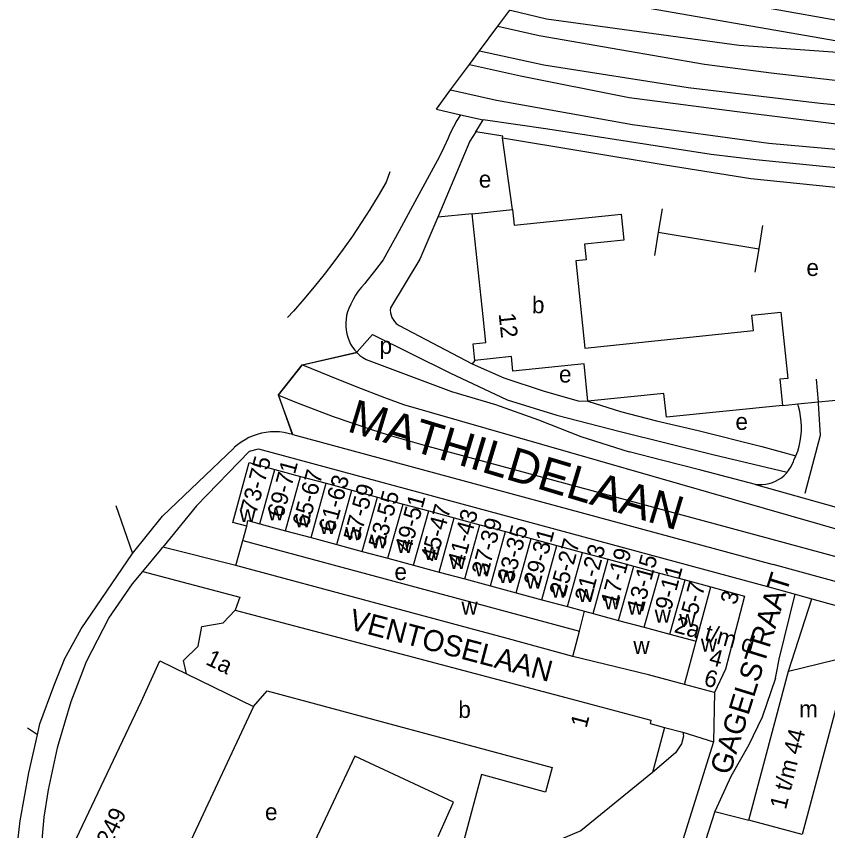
# Model space of a CAD drawing. Extents: x 160673 to 161924, y 382258 to 384145.
# Drawn here: x 160684.6 to 160877.2, y 383510.1 to 383703.4 of the extents above; entities that cross this region are included whole.
import ezdxf

# ---------------------------------------------------------------- set-up
doc = ezdxf.new("R2010")
doc.units = 0
for name, color, linetype in [('BLT_Basislijn', 7, 'Continuous'), ('BLT_Bebouwing', 7, 'Continuous'), ('BLT_Centroide', 7, 'Continuous'), ('BLT_Huisnummer', 7, 'Continuous'), ('BLT_Huisnummer_reeks', 7, 'Continuous'), ('BLT_Huisnummer_zonder_bebouwing', 7, 'Continuous'), ('BLT_Onderverdeling_panden', 7, 'Continuous'), ('BLT_Plantopo', 7, 'Continuous'), ('BLT_Spoorlijn', 7, 'Continuous'), ('BLT_Straatnaam', 7, 'Continuous'), ('BLT_Straatnaam_hoofdweg', 7, 'Continuous'), ('BLT_Vlakafsluiter', 7, 'Continuous')]:
    doc.layers.add(name, color=color, linetype=linetype)

msp = doc.modelspace()

# ---------------------------------------------------------------- linework, layer by layer
at = {"layer": 'BLT_Basislijn'}
for p, q in [((160784.31, 383681.42), (160790.04, 383680.08)), ((160790.04, 383680.08), (160795.38, 383678.83)), ((160793.67, 383676.01), (160795.38, 383678.83)), ((160802.36, 383657.57), (160800.02, 383674.62)), ((160784.45, 383669.14), (160779.18, 383659.38)), ((160773.28, 383666.54), (160772.4, 383664.07)), ((160792.82, 383656.58), (160784.62, 383655.77)), ((160837.89, 383657.72), (160836.97, 383652.2)), ((160861.71, 383653.74), (160860.79, 383648.23)), ((160836.97, 383652.2), (160836.05, 383646.69)), ((160836.97, 383652.2), (160860.79, 383648.23)), ((160860.79, 383648.23), (160859.87, 383642.72)), ((160767.63, 383621.93), (160787.93, 383614.4)), ((160793.39, 383621.74), (160792.83, 383620.95)), ((160874.45, 383617.29), (160874.92, 383611.89)), ((160820.27, 383612.09), (160828.01, 383609.62)), ((160874.92, 383611.89), (160881.75, 383612.54)), ((160866.47, 383611.08), (160869.42, 383611.36)), ((160869.42, 383611.36), (160870.04, 383611.42)), ((160870.04, 383611.42), (160874.92, 383611.89)), ((160750.17, 383604.14), (160750.23, 383604.13)), ((160750.23, 383604.13), (160864.24, 383573.3)), ((160736.23, 383600.95), (160719.33, 383584.74)), ((160739.98, 383600.19), (160742.09, 383600.77)), ((160742.09, 383600.77), (160863.78, 383567.86)), ((160781.39, 383601.65), (160863.02, 383579.54)), ((160727.38, 383587.23), (160739.98, 383600.19)), ((160869.14, 383598.04), (160869.6, 383599.06)), ((160727.38, 383587.23), (160719.36, 383577.38)), ((160738.36, 383578.98), (160739.29, 383582.38)), ((160863.02, 383579.54), (160901.21, 383569.2)), ((160736.74, 383573.06), (160719.36, 383577.38)), ((160863.78, 383567.86), (160869.47, 383566.26)), ((160867.86, 383547.96), (160873.42, 383565.14)), ((160873.42, 383565.14), (160885.87, 383561.63)), ((160864.76, 383546.29), (160865.16, 383548.28)), ((160850.32, 383542.91), (160850.1, 383531.24)), ((160838.45, 383534.64), (160842.81, 383533.52)), ((160842.81, 383533.52), (160850.1, 383531.24)), ((160841.03, 383528.62), (160835.61, 383523.91)), ((160850.39, 383514.63), (160842.89, 383491.44)), ((160850.39, 383514.63), (160858.45, 383512.62))]:
    msp.add_line(p, q, dxfattribs=at)
for points in [[(160827.47, 383712.33), (160848.19, 383708.12), (160880.3, 383702.37), (160918.98, 383698.8)], [(160790.04, 383680.08), (160789.16, 383678.66), (160788.35, 383677.2), (160787.61, 383675.7), (160787.09, 383674.5)], [(160940.73, 383664.63), (160927.19, 383664.82), (160902.61, 383665.8), (160883.17, 383667.06), (160860.14, 383669.36), (160849.53, 383670.59), (160810.77, 383676.62), (160795.38, 383678.83)], [(160793.67, 383676.01), (160792.25, 383673.76), (160784.62, 383655.77)], [(160800.02, 383674.62), (160800.07, 383674.95), (160793.67, 383676.01)], [(160787.09, 383674.5), (160786.08, 383672.32), (160785.01, 383670.19), (160784.45, 383669.14)], [(160800.02, 383674.62), (160838.61, 383668.19)], [(160838.61, 383668.19), (160858.92, 383664.92), (160882.17, 383662.58), (160903.94, 383660.75), (160931.32, 383660.4)], [(160772.4, 383664.07), (160770.49, 383660.81), (160768.52, 383657.59), (160766.48, 383654.41), (160764.37, 383651.27), (160762.2, 383648.19), (160759.96, 383645.14), (160757.65, 383642.15), (160755.29, 383639.21), (160752.86, 383636.31), (160750.37, 383633.47), (160748.96, 383631.92)], [(160779.18, 383659.38), (160775.48, 383652.5), (160771.68, 383645.62)], [(160784.62, 383655.77), (160780.38, 383645.78), (160773.39, 383634.23)], [(160771.68, 383645.62), (160769.62, 383642.9), (160767.48, 383640.23), (160767.29, 383640.01)], [(160767.29, 383640.01), (160766.5, 383639.12), (160765.78, 383638.18), (160765.11, 383637.2), (160764.52, 383636.18), (160763.99, 383635.11), (160763.56, 383634.07)], [(160763.56, 383634.07), (160763.25, 383633.25), (160763.01, 383632.41), (160762.86, 383631.55), (160762.78, 383630.68), (160762.78, 383629.8), (160762.86, 383628.93), (160763.02, 383628.07), (160763.26, 383627.23), (160763.58, 383626.42), (160763.96, 383625.63), (160764.42, 383624.89), (160764.95, 383624.19), (160765.41, 383623.67)], [(160773.39, 383634.23), (160773.36, 383633.65), (160773.41, 383633.06), (160773.54, 383632.49), (160773.74, 383631.94), (160774.02, 383631.43), (160774.37, 383630.96), (160774.77, 383630.53), (160775.23, 383630.17), (160775.5, 383630)], [(160775.5, 383630), (160792.83, 383620.95)], [(160765.41, 383623.67), (160769.15, 383627.91), (160787.52, 383618.8), (160801.09, 383612.41), (160812.86, 383608.77), (160827.89, 383604.88), (160849.92, 383599.42), (160867.55, 383595.19)], [(160765.41, 383623.67), (160765.45, 383623.63)], [(160765.45, 383623.63), (160765.53, 383623.54), (160766.17, 383622.95), (160766.87, 383622.41), (160767.63, 383621.93)], [(160752.48, 383620.73), (160752.56, 383620.7)], [(160752.56, 383620.7), (160758.95, 383618.07), (160765.44, 383615.49), (160771.96, 383612.98), (160776.48, 383611.29), (160881.61, 383581.05)], [(160792.83, 383620.95), (160800.34, 383617.62), (160809.91, 383614.41), (160817.98, 383612.16), (160820.27, 383612.09)], [(160787.93, 383614.4), (160798.31, 383611.31), (160808.55, 383607.68), (160818.61, 383603.65), (160830.07, 383600.03)], [(160746.81, 383613.55), (160746.87, 383613.53)], [(160746.87, 383613.53), (160751.12, 383611.78), (160755.46, 383610.08), (160759.83, 383608.46), (160764.22, 383606.91), (160768.64, 383605.43), (160773.09, 383604.04), (160777.56, 383602.72), (160781.39, 383601.65)], [(160869.6, 383599.06), (160870.04, 383600.24), (160870.38, 383601.38), (160870.64, 383602.54), (160870.82, 383603.71), (160870.92, 383604.9), (160870.94, 383606.09), (160870.89, 383607.27), (160870.75, 383608.45), (160870.53, 383609.62), (160870.24, 383610.78), (160870.04, 383611.42)], [(160871.83, 383590.25), (160875.44, 383604), (160874.95, 383611.54), (160874.92, 383611.89)], [(160828.01, 383609.62), (160836.5, 383607.43), (160846.44, 383605.13), (160861.5, 383601.31)], [(160750.17, 383604.14), (160749.15, 383604.43), (160748.11, 383604.63), (160747.05, 383604.76), (160745.99, 383604.8), (160744.93, 383604.77), (160743.87, 383604.65), (160742.83, 383604.46), (160741.8, 383604.19), (160740.8, 383603.84), (160739.83, 383603.42), (160738.89, 383602.93), (160737.99, 383602.36), (160737.13, 383601.73), (160736.32, 383601.04), (160736.23, 383600.95)], [(160861.5, 383601.31), (160869.6, 383599.06)], [(160860.01, 383592.29), (160847.03, 383595.72), (160838.07, 383597.97), (160830.07, 383600.03)], [(160867.55, 383595.19), (160867.9, 383595.62), (160868.36, 383596.3), (160868.74, 383597.02), (160869.05, 383597.77), (160869.14, 383598.04)], [(160860.01, 383592.29), (160860.83, 383592.27), (160861.65, 383592.27), (160862.46, 383592.35), (160863.26, 383592.51), (160864.04, 383592.75), (160864.79, 383593.06), (160865.51, 383593.45), (160866.18, 383593.9), (160866.81, 383594.42), (160867.39, 383594.99), (160867.55, 383595.19)], [(160712.16, 383575.89), (160719.33, 383584.74)], [(160714.64, 383571.67), (160718.83, 383576.72), (160719.36, 383577.38)], [(160700, 383558.06), (160712.16, 383575.89)], [(160941.01, 383549.42), (160929.52, 383553.39), (160912.82, 383559.96), (160900.62, 383563.32), (160864.24, 383573.3)], [(160700, 383546.98), (160701.27, 383550.27), (160706.59, 383560.53), (160712.17, 383568.68), (160714.64, 383571.67)], [(160714.64, 383571.67), (160737.69, 383565.52), (160736.59, 383562.49)], [(160865.16, 383548.28), (160865.66, 383550.82), (160869.47, 383566.26)], [(160869.47, 383566.26), (160873.42, 383565.14)], [(160689.63, 383532.89), (160690.21, 383535.51), (160693.58, 383544.64), (160696.17, 383550.97), (160700, 383558.06)], [(160694.43, 383529.74), (160694.61, 383530.61), (160697.62, 383540.81), (160700, 383546.98)], [(160864.76, 383546.29), (160861.64, 383537.08), (160858.47, 383530.46), (160854.16, 383522.99), (160850.39, 383514.63)], [(160684.61, 383490.86), (160684.61, 383499.58), (160685.09, 383508.32), (160685.57, 383512.46), (160687.62, 383523.88), (160689.63, 383532.89)], [(160842.81, 383533.52), (160842.93, 383532.55), (160842.45, 383530.73), (160841.03, 383528.62)], [(160850.1, 383531.24), (160828.79, 383463.13), (160828.19, 383459.76), (160828.59, 383456.34), (160829.47, 383453.28), (160831.32, 383450.35), (160833.59, 383447.68), (160835.3, 383445.08), (160835.79, 383442.16)], [(160697.47, 383475.43), (160692.31, 383484.12), (160690.54, 383491.16), (160690.31, 383502.5), (160691.21, 383513.34), (160692.23, 383519.82), (160694.43, 383529.74)]]:
    msp.add_lwpolyline(points, dxfattribs=at)
at = {"layer": 'BLT_Bebouwing'}
for p, q in [((160802.45, 383619.2), (160802.1, 383622.64)), ((160745.98, 383595.84), (160752.06, 383594.21)), ((160752.06, 383594.21), (160758.15, 383592.57)), ((160758.15, 383592.57), (160764.23, 383590.93)), ((160764.23, 383590.93), (160770.31, 383589.29)), ((160770.31, 383589.29), (160776.4, 383587.65)), ((160776.4, 383587.65), (160782.48, 383586.01)), ((160782.48, 383586.01), (160788.56, 383584.37)), ((160742.38, 383582.97), (160748.47, 383581.33)), ((160788.56, 383584.37), (160794.65, 383582.74)), ((160748.47, 383581.33), (160754.55, 383579.69)), ((160794.65, 383582.74), (160800.73, 383581.1)), ((160800.73, 383581.1), (160806.81, 383579.46)), ((160754.55, 383579.69), (160760.64, 383578.06)), ((160806.81, 383579.46), (160812.9, 383577.82)), ((160736.74, 383573.06), (160738.36, 383578.98)), ((160738.36, 383578.98), (160818.25, 383557.46)), ((160760.64, 383578.06), (160766.72, 383576.42)), ((160812.9, 383577.82), (160818.98, 383576.18)), ((160766.72, 383576.42), (160772.8, 383574.78)), ((160818.98, 383576.18), (160825.07, 383574.54)), ((160772.8, 383574.78), (160778.89, 383573.14)), ((160825.07, 383574.54), (160831.15, 383572.9)), ((160778.89, 383573.14), (160784.97, 383571.5)), ((160784.97, 383571.5), (160791.05, 383569.86)), ((160831.15, 383572.9), (160837.23, 383571.26)), ((160791.05, 383569.86), (160797.14, 383568.22)), ((160837.23, 383571.26), (160843.32, 383569.63)), ((160843.32, 383569.63), (160849.4, 383567.99)), ((160797.14, 383568.22), (160803.22, 383566.59)), ((160803.22, 383566.59), (160809.3, 383564.95)), ((160857.46, 383565.82), (160853.81, 383551.75)), ((160809.3, 383564.95), (160815.39, 383563.31)), ((160736.59, 383562.49), (160749.16, 383559.16)), ((160815.39, 383563.31), (160819.48, 383562.21)), ((160818.25, 383557.46), (160819.48, 383562.21)), ((160749.16, 383559.16), (160777.39, 383551.68)), ((160724.99, 383547.34), (160724.26, 383550.5)), ((160777.39, 383551.68), (160815.05, 383541.71)), ((160858.45, 383512.62), (160867.86, 383547.96)), ((160838.45, 383534.64), (160835.61, 383523.91))]:
    msp.add_line(p, q, dxfattribs=at)
for points in [[(160792.82, 383656.58), (160802.36, 383657.57)], [(160795.42, 383632.17), (160792.82, 383656.58)], [(160802.36, 383657.57), (160802.75, 383653.82), (160826.68, 383656.32)], [(160826.68, 383656.32), (160828.16, 383656.48), (160828.8, 383650.32), (160819.42, 383649.34), (160819.81, 383645.63), (160817.36, 383645.37), (160819.52, 383624.68), (160859.52, 383628.86), (160859.14, 383632.45), (160866.05, 383633.17), (160867.7, 383617.45), (160865.83, 383617.26), (160866.47, 383611.08)], [(160793.39, 383621.74), (160793.04, 383625.72), (160796.06, 383626.03), (160795.42, 383632.17)], [(160802.1, 383622.64), (160793.39, 383621.74)], [(160820.27, 383612.09), (160819.37, 383620.92), (160802.45, 383619.2)], [(160838.3, 383613.93), (160820.27, 383612.09)], [(160866.47, 383611.08), (160838.88, 383608.3), (160838.3, 383613.93)], [(160739.29, 383582.38), (160735.99, 383583.28), (160739.89, 383597.5), (160745.98, 383595.84)], [(160739.29, 383582.38), (160739.57, 383583.73), (160742.38, 383582.97)], [(160816.68, 383551.44), (160801.43, 383555.62), (160736.74, 383573.06)], [(160849.4, 383567.99), (160857.46, 383565.82)], [(160728.61, 383558.56), (160733.67, 383559.48), (160736.59, 383562.49)], [(160724.26, 383550.5), (160727.77, 383553.89), (160728.61, 383558.56)], [(160843.17, 383544.85), (160834.65, 383547.07), (160816.68, 383551.44)], [(160853.81, 383551.75), (160852.92, 383548.47), (160850.32, 383542.91), (160843.17, 383544.85)], [(160867.86, 383547.96), (160882.4, 383551.52), (160871.13, 383509.23), (160858.45, 383512.62)], [(160724.99, 383547.34), (160740.93, 383539.56), (160744.15, 383543.28), (160811.79, 383525.14), (160810.21, 383519.26), (160794.99, 383523.45), (160790.82, 383507.82)], [(160815.05, 383541.71), (160835.22, 383536.36), (160835.01, 383535.55), (160838.45, 383534.64)], [(160835.61, 383523.91), (160818.62, 383510.07), (160804.56, 383504.15), (160790.82, 383507.82)]]:
    msp.add_lwpolyline(points, dxfattribs=at)
at = {"layer": 'BLT_Onderverdeling_panden'}
for p, q in [((160742.38, 383582.97), (160745.98, 383595.84)), ((160748.47, 383581.33), (160752.06, 383594.21)), ((160754.55, 383579.69), (160758.15, 383592.57)), ((160760.64, 383578.06), (160764.23, 383590.93)), ((160766.72, 383576.42), (160770.31, 383589.29)), ((160772.8, 383574.78), (160776.4, 383587.65)), ((160778.89, 383573.14), (160782.48, 383586.01)), ((160784.97, 383571.5), (160788.56, 383584.37)), ((160791.05, 383569.86), (160794.65, 383582.74)), ((160797.14, 383568.22), (160800.73, 383581.1)), ((160803.22, 383566.59), (160806.81, 383579.46)), ((160809.3, 383564.95), (160812.9, 383577.82)), ((160815.39, 383563.31), (160818.98, 383576.18)), ((160821.47, 383561.67), (160825.07, 383574.54)), ((160827.55, 383560.03), (160831.15, 383572.9)), ((160833.64, 383558.39), (160837.23, 383571.26)), ((160839.72, 383556.76), (160843.32, 383569.63)), ((160845.93, 383555.08), (160849.4, 383567.99)), ((160819.48, 383562.21), (160821.47, 383561.67)), ((160821.47, 383561.67), (160827.55, 383560.03)), ((160827.55, 383560.03), (160833.64, 383558.39)), ((160833.64, 383558.39), (160839.72, 383556.76)), ((160816.68, 383551.44), (160818.25, 383557.46)), ((160839.72, 383556.76), (160845.93, 383555.08)), ((160843.17, 383544.85), (160845.93, 383555.08))]:
    msp.add_line(p, q, dxfattribs=at)
at = {"layer": 'BLT_Plantopo'}
msp.add_lwpolyline([(160695.94, 383502.2), (160714.21, 383540.7), (160718.7, 383550.41), (160740.93, 383539.56), (160726.08, 383507.92), (160750.26, 383496.57), (160742.55, 383480.14)], close=True, dxfattribs=at)
msp.add_lwpolyline([(160784.69, 383508.72), (160788.4, 383516.92), (160764.92, 383527.8), (160750.26, 383496.57)], dxfattribs=at)
at = {"layer": 'BLT_Spoorlijn'}
for points in [[(160888.5, 383695.98), (160832.94, 383705.59), (160805.98, 383710.64)], [(160801.71, 383704.89), (160802.24, 383704.78), (160810.45, 383702.83)], [(160810.45, 383702.83), (160856.18, 383696.58), (160897.27, 383693.67), (160932.99, 383691.66), (160956.62, 383691.24)], [(160798.89, 383701.08), (160808.69, 383698.88)], [(160808.69, 383698.88), (160827.84, 383695.56), (160847.92, 383692.06), (160863.75, 383690.03), (160885.85, 383687.51), (160921.52, 383685.06), (160957.39, 383684.76)], [(160794.54, 383695.22), (160809.8, 383691.88)], [(160787.69, 383685.98), (160798.55, 383683.51), (160830.88, 383677.77), (160863.18, 383673.34), (160888.88, 383671.04), (160918.45, 383669.84), (160955.11, 383670.29), (160991.96, 383672.56), (161075.17, 383681.29), (161131.02, 383687.39), (161179.48, 383692.52)], [(160792.16, 383692), (160804.27, 383689.3)], [(160809.8, 383691.88), (160844.05, 383686.53), (160875.35, 383682.85), (160904.27, 383680.06), (160934.72, 383679.23), (160957.76, 383679.51)], [(160804.27, 383689.3), (160830.05, 383684.14), (160855.65, 383680.82), (160879.22, 383677.89), (160905.19, 383675.87), (160930.97, 383674.75), (160958.31, 383674.84)]]:
    msp.add_lwpolyline(points, dxfattribs=at)
at = {"layer": 'BLT_Vlakafsluiter'}
for p, q in [((160798.89, 383701.08), (160801.71, 383704.89)), ((160794.54, 383695.22), (160798.89, 383701.08)), ((160792.16, 383692), (160794.54, 383695.22)), ((160787.69, 383685.98), (160792.16, 383692)), ((160784.31, 383681.42), (160787.69, 383685.98)), ((160752.56, 383620.7), (160765.45, 383623.63)), ((160746.87, 383613.53), (160752.56, 383620.7)), ((160750.23, 383604.13), (160746.87, 383613.53)), ((160860.01, 383592.29), (160882.94, 383585.87)), ((160708.27, 383587.31), (160712.16, 383575.89)), ((160689.63, 383532.89), (160687.25, 383534.45))]:
    msp.add_line(p, q, dxfattribs=at)
for points in [[(160752.48, 383620.73), (160765.41, 383623.67)], [(160746.81, 383613.55), (160752.48, 383620.73)], [(160750.17, 383604.14), (160746.81, 383613.55)]]:
    msp.add_lwpolyline(points, dxfattribs=at)

# ---------------------------------------------------------------- texts
at = {"layer": 'BLT_Centroide'}
for s, p in [('e', (160794.37, 383662.77)), ('e', (160872.12, 383641.79)), ('b', (160806.99, 383632.94)), ('p', (160770.81, 383623.29)), ('e', (160813.4, 383616.5)), ('e', (160855.27, 383605.25)), ('w', (160744.3, 383583.75)), ('w', (160737.59, 383583.36)), ('w', (160750.7, 383582.14)), ('w', (160756.61, 383580.51)), ('w', (160762.72, 383579.13)), ('w', (160768.77, 383577.14)), ('w', (160774.86, 383576.03)), ('w', (160781.35, 383574.4)), ('w', (160787.42, 383572.23)), ('w', (160793.42, 383570.51)), ('e', (160774.35, 383569.61)), ('w', (160799.03, 383568.87)), ('w', (160805.57, 383567.56)), ('w', (160811.55, 383565.43)), ('w', (160817.93, 383564.39)), ('w', (160824.09, 383562.63)), ('w', (160790.25, 383561.38)), ('w', (160829.7, 383561.4)), ('w', (160836.11, 383559.5)), ('w', (160841.95, 383558.44)), ('w', (160831.05, 383552.05)), ('w', (160847.07, 383552.62)), ('b', (160789.51, 383536.87)), ('m', (160870.37, 383537.02)), ('e', (160743.63, 383512.59))]:
    msp.add_text(s, height=4, dxfattribs=at).set_placement(p)
at = {"layer": 'BLT_Huisnummer'}
msp.add_text('12', height=4, rotation=276.0711, dxfattribs=at).set_placement((160799.07, 383632.83))
at = {"layer": 'BLT_Huisnummer_reeks'}
for s, rotation, p in [('73-75', 74.8091, (160741.55, 383585.15)), ('69-71', 74.8074, (160747.91, 383584.23)), ('65-67', 74.8074, (160753.89, 383581.93)), ('61-63', 74.8088, (160760.09, 383580.71)), ('57-59', 74.8088, (160766.03, 383578.61)), ('53-55', 74.8093, (160771.95, 383576.96)), ('49-51', 74.8093, (160778.19, 383576.13)), ('45-47', 74.8069, (160784.28, 383573.73)), ('41-43', 74.8069, (160790.66, 383572.58)), ('37-39', 74.8074, (160796.42, 383570.52)), ('33-35', 74.8069, (160802.52, 383568.8)), ('29-31', 74.8069, (160808.76, 383567.95)), ('25-27', 74.8078, (160814.85, 383565.56)), ('21-23', 74.8078, (160820.89, 383564.24)), ('17-19', 74.8093, (160827.08, 383563.34)), ('13-15', 74.8093, (160833.25, 383561.8)), ('9-11', 74.8086, (160839.97, 383562.2)), ('5-7', 74.8086, (160846.19, 383561.09)), ('3', 75.3635, (160855.48, 383563.57)), ('2a t/m d', 344.8028, (160840.53, 383557.26)), ('1a', 334.038, (160729.31, 383549.72)), ('4', 344.8028, (160848.77, 383549.61)), ('6', 344.8028, (160847.54, 383544.67)), ('1', 75.1639, (160819.91, 383534.32)), ('1 t/m 44', 76, (160867.23, 383514.96))]:
    msp.add_text(s, height=4, rotation=rotation, dxfattribs=at).set_placement(p)
at = {"layer": 'BLT_Huisnummer_zonder_bebouwing'}
msp.add_text('21 249', height=4, rotation=64.4065, dxfattribs=at).set_placement((160703.81, 383499.54))
at = {"layer": 'BLT_Straatnaam'}
for s, height, rotation, p in [('GAGELSTRAAT', 5, 72.7482, (160853.92, 383523.1)), ('VENTOSELAAN', 4.9999, 345.2026, (160763.28, 383558.02))]:
    msp.add_text(s, height=height, rotation=rotation, dxfattribs=at).set_placement(p)
at = {"layer": 'BLT_Straatnaam_hoofdweg'}
msp.add_text('MATHILDELAAN', height=8, rotation=343.279, dxfattribs=at).set_placement((160762.86, 383604.97))

doc.saveas('drawing.dxf')
